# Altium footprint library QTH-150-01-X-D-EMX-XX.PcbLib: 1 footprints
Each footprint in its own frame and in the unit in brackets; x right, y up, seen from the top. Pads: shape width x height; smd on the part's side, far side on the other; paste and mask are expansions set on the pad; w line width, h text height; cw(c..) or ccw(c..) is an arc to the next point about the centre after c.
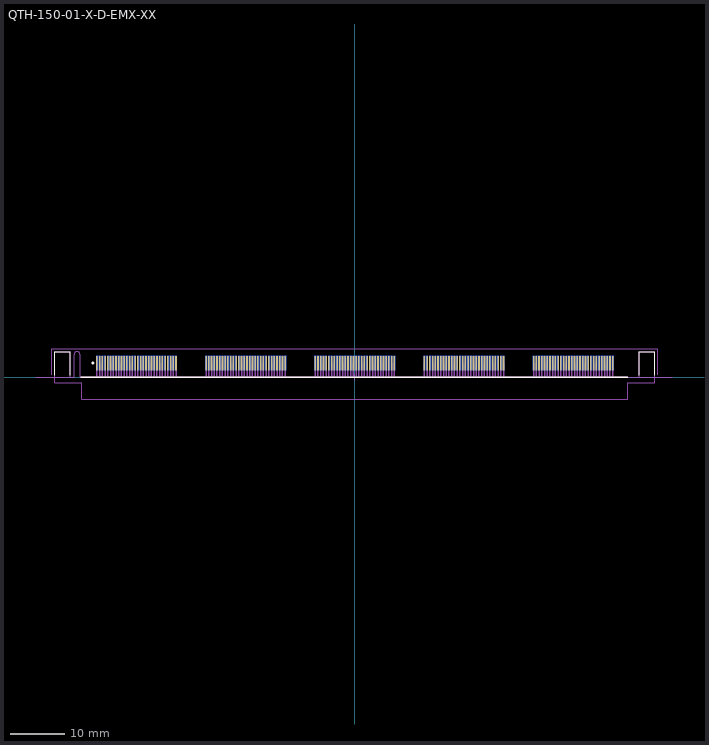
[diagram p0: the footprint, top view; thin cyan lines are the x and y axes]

## QTH-150-01-X-D-EMX-XX [mm] "0.50mm pitch, 300 pin, high speed terminal; w/edge mounts"
height 3.62
pads (300):
  rect 0.3x2.65 smd mask+0: 1(-47.256,2.6) 3(-46.756,2.6) 5(-46.256,2.6) 7(-45.756,2.6) 9(-45.256,2.6) 11(-44.756,2.6) 13(-44.256,2.6) 15(-43.756,2.6) 17(-43.256,2.6) 19(-42.756,2.6) 21(-42.256,2.6) 23(-41.756,2.6) 25(-41.256,2.6) 27(-40.756,2.6) 29(-40.256,2.6) 31(-39.756,2.6) 33(-39.256,2.6) 35(-38.756,2.6) 37(-38.256,2.6) 39(-37.756,2.6) 41(-37.256,2.6) 43(-36.756,2.6) 45(-36.256,2.6) 47(-35.756,2.6) 49(-35.256,2.6) 51(-34.756,2.6) 53(-34.256,2.6) 55(-33.756,2.6) 57(-33.256,2.6) 59(-32.756,2.6) 61(-27.253,2.6) 63(-26.753,2.6) 65(-26.253,2.6) 67(-25.753,2.6) 69(-25.253,2.6) 71(-24.753,2.6) 73(-24.253,2.6) 75(-23.753,2.6) 77(-23.253,2.6) 79(-22.753,2.6) 81(-22.253,2.6) 83(-21.753,2.6) 85(-21.253,2.6) 87(-20.753,2.6) 89(-20.253,2.6) 91(-19.753,2.6) 93(-19.253,2.6) 95(-18.753,2.6) 97(-18.253,2.6) 99(-17.753,2.6) 101(-17.253,2.6) 103(-16.753,2.6) 105(-16.253,2.6) 107(-15.753,2.6) 109(-15.253,2.6) 111(-14.753,2.6) 113(-14.253,2.6) 115(-13.753,2.6) 117(-13.253,2.6) 119(-12.753,2.6) 121(-7.25,2.6) 123(-6.75,2.6) 125(-6.25,2.6) 127(-5.75,2.6) 129(-5.25,2.6) 131(-4.75,2.6) 133(-4.25,2.6) 135(-3.75,2.6) 137(-3.25,2.6) 139(-2.75,2.6) 141(-2.25,2.6) 143(-1.75,2.6) 145(-1.25,2.6) 147(-0.75,2.6) 149(-0.25,2.6) 151(0.25,2.6) 153(0.75,2.6) 155(1.25,2.6) 157(1.75,2.6) 159(2.25,2.6) 161(2.75,2.6) 163(3.25,2.6) 165(3.75,2.6) 167(4.25,2.6) 169(4.75,2.6) 171(5.25,2.6) 173(5.75,2.6) 175(6.25,2.6) 177(6.75,2.6) 179(7.25,2.6) 181(12.753,2.6) 183(13.253,2.6) 185(13.753,2.6) 187(14.253,2.6) 189(14.753,2.6) 191(15.253,2.6) 193(15.753,2.6) 195(16.253,2.6) 197(16.753,2.6) 199(17.253,2.6) 201(17.753,2.6) 203(18.253,2.6) 205(18.753,2.6) 207(19.253,2.6) 209(19.753,2.6) 211(20.253,2.6) 213(20.753,2.6) 215(21.253,2.6) 217(21.753,2.6) 219(22.253,2.6) 221(22.753,2.6) 223(23.253,2.6) 225(23.753,2.6) 227(24.253,2.6) 229(24.753,2.6) 231(25.253,2.6) 233(25.753,2.6) 235(26.253,2.6) 237(26.753,2.6) 239(27.253,2.6) 241(32.756,2.6) 243(33.256,2.6) 245(33.756,2.6) 247(34.256,2.6) 249(34.756,2.6) 251(35.256,2.6) 253(35.756,2.6) 255(36.256,2.6) 257(36.756,2.6) 259(37.256,2.6) 261(37.756,2.6) 263(38.256,2.6) 265(38.756,2.6) 267(39.256,2.6) 269(39.756,2.6) 271(40.256,2.6) 273(40.756,2.6) 275(41.256,2.6) 277(41.756,2.6) 279(42.256,2.6) 281(42.756,2.6) 283(43.256,2.6) 285(43.756,2.6) 287(44.256,2.6) 289(44.756,2.6) 291(45.256,2.6) 293(45.756,2.6) 295(46.256,2.6) 297(46.756,2.6) 299(47.256,2.6)
  rect 0.3x2.65 smd far side mask+0: 2(-47.256,2.6) 4(-46.756,2.6) 6(-46.256,2.6) 8(-45.756,2.6) 10(-45.256,2.6) 12(-44.756,2.6) 14(-44.256,2.6) 16(-43.756,2.6) 18(-43.256,2.6) 20(-42.756,2.6) 22(-42.256,2.6) 24(-41.756,2.6) 26(-41.256,2.6) 28(-40.756,2.6) 30(-40.256,2.6) 32(-39.756,2.6) 34(-39.256,2.6) 36(-38.756,2.6) 38(-38.256,2.6) 40(-37.756,2.6) 42(-37.256,2.6) 44(-36.756,2.6) 46(-36.256,2.6) 48(-35.756,2.6) 50(-35.256,2.6) 52(-34.756,2.6) 54(-34.256,2.6) 56(-33.756,2.6) 58(-33.256,2.6) 60(-32.756,2.6) 62(-27.253,2.6) 64(-26.753,2.6) 66(-26.253,2.6) 68(-25.753,2.6) 70(-25.253,2.6) 72(-24.753,2.6) 74(-24.253,2.6) 76(-23.753,2.6) 78(-23.253,2.6) 80(-22.753,2.6) 82(-22.253,2.6) 84(-21.753,2.6) 86(-21.253,2.6) 88(-20.753,2.6) 90(-20.253,2.6) 92(-19.753,2.6) 94(-19.253,2.6) 96(-18.753,2.6) 98(-18.253,2.6) 100(-17.753,2.6) 102(-17.253,2.6) 104(-16.753,2.6) 106(-16.253,2.6) 108(-15.753,2.6) 110(-15.253,2.6) 112(-14.753,2.6) 114(-14.253,2.6) 116(-13.753,2.6) 118(-13.253,2.6) 120(-12.753,2.6) 122(-7.25,2.6) 124(-6.75,2.6) 126(-6.25,2.6) 128(-5.75,2.6) 130(-5.25,2.6) 132(-4.75,2.6) 134(-4.25,2.6) 136(-3.75,2.6) 138(-3.25,2.6) 140(-2.75,2.6) 142(-2.25,2.6) 144(-1.75,2.6) 146(-1.25,2.6) 148(-0.75,2.6) 150(-0.25,2.6) 152(0.25,2.6) 154(0.75,2.6) 156(1.25,2.6) 158(1.75,2.6) 160(2.25,2.6) 162(2.75,2.6) 164(3.25,2.6) 166(3.75,2.6) 168(4.25,2.6) 170(4.75,2.6) 172(5.25,2.6) 174(5.75,2.6) 176(6.25,2.6) 178(6.75,2.6) 180(7.25,2.6) 182(12.753,2.6) 184(13.253,2.6) 186(13.753,2.6) 188(14.253,2.6) 190(14.753,2.6) 192(15.253,2.6) 194(15.753,2.6) 196(16.253,2.6) 198(16.753,2.6) 200(17.253,2.6) 202(17.753,2.6) 204(18.253,2.6) 206(18.753,2.6) 208(19.253,2.6) 210(19.753,2.6) 212(20.253,2.6) 214(20.753,2.6) 216(21.253,2.6) 218(21.753,2.6) 220(22.253,2.6) 222(22.753,2.6) 224(23.253,2.6) 226(23.753,2.6) 228(24.253,2.6) 230(24.753,2.6) 232(25.253,2.6) 234(25.753,2.6) 236(26.253,2.6) 238(26.753,2.6) 240(27.253,2.6) 242(32.756,2.6) 244(33.256,2.6) 246(33.756,2.6) 248(34.256,2.6) 250(34.756,2.6) 252(35.256,2.6) 254(35.756,2.6) 256(36.256,2.6) 258(36.756,2.6) 260(37.256,2.6) 262(37.756,2.6) 264(38.256,2.6) 266(38.756,2.6) 268(39.256,2.6) 270(39.756,2.6) 272(40.256,2.6) 274(40.756,2.6) 276(41.256,2.6) 278(41.756,2.6) 280(42.256,2.6) 282(42.756,2.6) 284(43.256,2.6) 286(43.756,2.6) 288(44.256,2.6) 290(44.756,2.6) 292(45.256,2.6) 294(45.756,2.6) 296(46.256,2.6) 298(46.756,2.6) 300(47.256,2.6)
Top Overlay:
  circle w0.25: c-48,2.6 r0.125
  lines w0.2: -55,0.4 -55,4.7 -52.1,4.7 -52.1,0.4 ; 52.1,0.4 52.1,4.7 55,4.7 55,0.4
  lines w0.25: -50.2,0 50,0
Top Paste:
  lines w0.4: -50.22,0 50,0
Bottom Paste:
  lines w0.381: -50.22,0 50,0
Top Solder:
  lines w0.127: -47.256,2.603 -47.256,3.936 ; -46.756,2.603 -46.756,3.936 ; -46.256,2.603 -46.256,3.936 ; -45.756,2.603 -45.756,3.936 ; -45.256,2.603 -45.256,3.936 ; -44.756,2.603 -44.756,3.936 ; -44.256,2.603 -44.256,3.936 ; -43.756,2.603 -43.756,3.936 ; -43.256,2.603 -43.256,3.936 ; -42.756,2.603 -42.756,3.936 ; -42.256,2.603 -42.256,3.936 ; -41.756,2.603 -41.756,3.936 ; -41.256,2.603 -41.256,3.936 ; -40.756,2.603 -40.756,3.936 ; -40.256,2.603 -40.256,3.936 ; -39.756,2.603 -39.756,3.936 ; -39.256,2.603 -39.256,3.936 ; -38.756,2.603 -38.756,3.936 ; -38.256,2.603 -38.256,3.936 ; -37.756,2.603 -37.756,3.936 ; -37.256,2.603 -37.256,3.936 ; -36.756,2.603 -36.756,3.936 ; -36.256,2.603 -36.256,3.936 ; -35.756,2.603 -35.756,3.936 ; -35.256,2.603 -35.256,3.936 ; -34.756,2.603 -34.756,3.936 ; -34.256,2.603 -34.256,3.936 ; -33.756,2.603 -33.756,3.936 ; -33.256,2.603 -33.256,3.936 ; -32.756,2.603 -32.756,3.936 ; -27.253,2.603 -27.253,3.936 ; -26.753,2.603 -26.753,3.936 ; -26.253,2.603 -26.253,3.936 ; -25.753,2.603 -25.753,3.936 ; -25.253,2.603 -25.253,3.936 ; -24.753,2.603 -24.753,3.936 ; -24.253,2.603 -24.253,3.936 ; -23.753,2.603 -23.753,3.936 ; -23.253,2.603 -23.253,3.936 ; -22.753,2.603 -22.753,3.936 ; -22.253,2.603 -22.253,3.936 ; -21.753,2.603 -21.753,3.936 ; -21.253,2.603 -21.253,3.936 ; -20.753,2.603 -20.753,3.936 ; -20.253,2.603 -20.253,3.936 ; -19.753,2.603 -19.753,3.936 ; -19.253,2.603 -19.253,3.936 ; -18.753,2.603 -18.753,3.936 ; -18.253,2.603 -18.253,3.936 ; -17.753,2.603 -17.753,3.936 ; -17.253,2.603 -17.253,3.936 ; -16.753,2.603 -16.753,3.936 ; -16.253,2.603 -16.253,3.936 ; -15.753,2.603 -15.753,3.936 ; -15.253,2.603 -15.253,3.936 ; -14.753,2.603 -14.753,3.936 ; -14.253,2.603 -14.253,3.936 ; -13.753,2.603 -13.753,3.936 ; -13.253,2.603 -13.253,3.936 ; -12.753,2.603 -12.753,3.936 ; -7.25,2.603 -7.25,3.936 ; -6.75,2.603 -6.75,3.936 ; -6.25,2.603 -6.25,3.936 ; -5.75,2.603 -5.75,3.936 ; -5.25,2.603 -5.25,3.936 ; -4.75,2.603 -4.75,3.936 ; -4.25,2.603 -4.25,3.936 ; -3.75,2.603 -3.75,3.936 ; -3.25,2.603 -3.25,3.936 ; -2.75,2.603 -2.75,3.936 ; -2.25,2.603 -2.25,3.936 ; -1.75,2.603 -1.75,3.936 ; -1.25,2.603 -1.25,3.936 ; -0.75,2.603 -0.75,3.936 ; -0.25,2.603 -0.25,3.936 ; 0.25,2.603 0.25,3.936 ; 0.75,2.603 0.75,3.936 ; 1.25,2.603 1.25,3.936 ; 1.75,2.603 1.75,3.936 ; 2.25,2.603 2.25,3.936 ; 2.75,2.603 2.75,3.936 ; 3.25,2.603 3.25,3.936 ; 3.75,2.603 3.75,3.936 ; 4.25,2.603 4.25,3.936 ; 4.75,2.603 4.75,3.936 ; 5.25,2.603 5.25,3.936 ; 5.75,2.603 5.75,3.936 ; 6.25,2.603 6.25,3.936 ; 6.75,2.603 6.75,3.936 ; 7.25,2.603 7.25,3.936 ; 12.753,2.603 12.753,3.936 ; 13.253,2.603 13.253,3.936 ; 13.753,2.603 13.753,3.936 ; 14.253,2.603 14.253,3.936 ; 14.753,2.603 14.753,3.936 ; 15.253,2.603 15.253,3.936 ; 15.753,2.603 15.753,3.936 ; 16.253,2.603 16.253,3.936 ; 16.753,2.603 16.753,3.936 ; 17.253,2.603 17.253,3.936 ; 17.753,2.603 17.753,3.936 ; 18.253,2.603 18.253,3.936 ; 18.753,2.603 18.753,3.936 ; 19.253,2.603 19.253,3.936 ; 19.753,2.603 19.753,3.936 ; 20.253,2.603 20.253,3.936 ; 20.753,2.603 20.753,3.936 ; 21.253,2.603 21.253,3.936 ; 21.753,2.603 21.753,3.936 ; 22.253,2.603 22.253,3.936 ; 22.753,2.603 22.753,3.936 ; 23.253,2.603 23.253,3.936 ; 23.753,2.603 23.753,3.936 ; 24.253,2.603 24.253,3.936 ; 24.753,2.603 24.753,3.936 ; 25.253,2.603 25.253,3.936 ; 25.753,2.603 25.753,3.936 ; 26.253,2.603 26.253,3.936 ; 26.753,2.603 26.753,3.936 ; 27.253,2.603 27.253,3.936 ; 32.756,2.603 32.756,3.936 ; 33.256,2.603 33.256,3.936 ; 33.756,2.603 33.756,3.936 ; 34.256,2.603 34.256,3.936 ; 34.756,2.603 34.756,3.936 ; 35.256,2.603 35.256,3.936 ; 35.756,2.603 35.756,3.936 ; 36.256,2.603 36.256,3.936 ; 36.756,2.603 36.756,3.936 ; 37.256,2.603 37.256,3.936 ; 37.756,2.603 37.756,3.936 ; 38.256,2.603 38.256,3.936 ; 38.756,2.603 38.756,3.936 ; 39.256,2.603 39.256,3.936 ; 39.756,2.603 39.756,3.936 ; 40.256,2.603 40.256,3.936 ; 40.756,2.603 40.756,3.936 ; 41.256,2.603 41.256,3.936 ; 41.756,2.603 41.756,3.936 ; 42.256,2.603 42.256,3.936 ; 42.756,2.603 42.756,3.936 ; 43.256,2.603 43.256,3.936 ; 43.756,2.603 43.756,3.936 ; 44.256,2.603 44.256,3.936 ; 44.756,2.603 44.756,3.936 ; 45.256,2.603 45.256,3.936 ; 45.756,2.603 45.756,3.936 ; 46.256,2.603 46.256,3.936 ; 46.756,2.603 46.756,3.936 ; 47.256,2.603 47.256,3.936
Bottom Solder:
  drawing of 450 lines, arcs and shapes, not listed
Mechanical 4:
  lines w0.25: -50.22,0 50,0
Mechanical 12:
  lines w0.001: -58.45,0 -51.45,0 -51.45,4.15 ; -50.35,4.15 -50.35,0 58.15,0
Mechanical 13:
  drawing of 166 lines, arcs and shapes, not listed
  text ".Designator" at 0,0 h1.52
Mechanical 15:
  lines w0.05: -55.5,0.5 -55.5,5.2 55.5,5.2 55.5,0.5 ; -0.5,0 0.5,0 ; 0,-0.5 0,0.5
Drill Drawing:
  lines w0.001: -51.45,4.15 cw(c-50.9,4.15) -50.35,4.15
